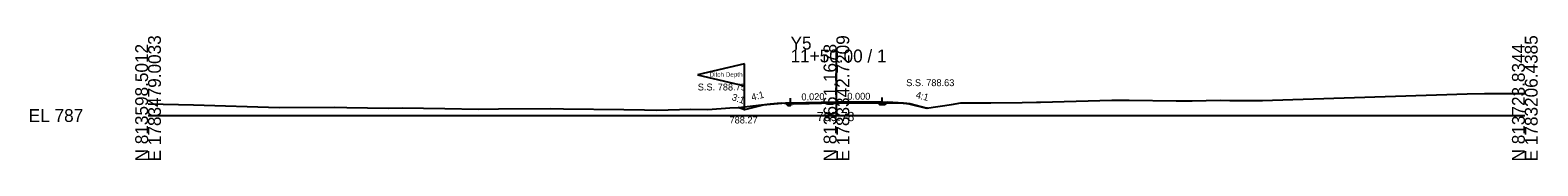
# Model space of a CAD drawing. Extents: x -26 to 1603, y -10 to 6526.
# Drawn here: x -25.7 to 302.8, y 1990.3 to 2017.3 of the extents above; entities that cross this region are included whole.
import ezdxf

# ---------------------------------------------------------------- set-up
doc = ezdxf.new("R2010")
doc.units = 0
for name, color, linetype in [('Exist Cross Section Cell', 7, 'Continuous'), ('Exist XS Center Line Elevation Label', 7, 'Continuous'), ('Exist XS Ground Line', 7, 'Continuous'), ('Prop XS Ditch Slope Text', 7, 'Continuous'), ('Prop XS Ditch Standard Text', 7, 'Continuous'), ('Prop XS Dump Level', 7, 'Continuous'), ('Prop XS Earthwork Shape', 7, 'Continuous'), ('Prop XS EOT Tick Mark', 7, 'Continuous'), ('Prop XS Finish Grade', 7, 'Continuous'), ('Prop XS Finish Grade Earthwork', 7, 'Continuous'), ('Prop XS Finish Grade Pavement', 7, 'Continuous'), ('Prop XS Pvmt Edge Slope', 7, 'Continuous'), ('Prop XS SE Text', 7, 'Continuous'), ('Prop XS Side Slope Text', 7, 'Continuous'), ('Prop XS SS Elevation Text', 7, 'Continuous'), ('Prop XS Subgrade Earthwork', 7, 'Continuous')]:
    doc.layers.add(name, color=color, linetype=linetype)

msp = doc.modelspace()

# ---------------------------------------------------------------- linework, layer by layer
at = {"layer": 'Exist Cross Section Cell'}
for p, q in [((150, 2000), (150, 2014.38)), ((0, 2000), (150, 2000)), ((150, 2000), (300, 2000))]:
    msp.add_line(p, q, dxfattribs=at)
at = {"layer": 'Exist XS Ground Line'}
for p, q in [((245.04, 2003.32), (287.47, 2004.72)), ((287.47, 2004.72), (291.25, 2004.78)), ((291.25, 2004.78), (300, 2004.79)), ((0, 2002.55), (9.93, 2002.34)), ((9.93, 2002.34), (28.54, 2001.74)), ((28.54, 2001.74), (40.53, 2001.79)), ((40.53, 2001.79), (43.29, 2001.78)), ((43.29, 2001.78), (52.34, 2001.6)), ((52.34, 2001.6), (55.39, 2001.7)), ((55.39, 2001.7), (64.65, 2001.51)), ((64.65, 2001.51), (72.02, 2001.42)), ((72.02, 2001.42), (76.39, 2001.47)), ((76.39, 2001.47), (87.61, 2001.52)), ((87.61, 2001.52), (90.51, 2001.47)), ((90.51, 2001.47), (103.64, 2001.29)), ((103.64, 2001.29), (108.15, 2001.23)), ((108.15, 2001.23), (110.85, 2001.18)), ((110.85, 2001.18), (118.3, 2001.42)), ((118.3, 2001.42), (121.96, 2001.31)), ((121.96, 2001.31), (126.77, 2001.69)), ((126.77, 2001.69), (128.69, 2001.75)), ((128.69, 2001.75), (135.59, 2002.58)), ((135.59, 2002.58), (137.08, 2002.68)), ((137.08, 2002.68), (138.08, 2002.75)), ((138.08, 2002.75), (139.86, 2002.56)), ((139.86, 2002.56), (144.06, 2002.65)), ((144.06, 2002.65), (149.46, 2002.78)), ((149.46, 2002.78), (150, 2002.78)), ((150, 2002.78), (157.1, 2002.78)), ((157.1, 2002.78), (159.36, 2002.78)), ((159.36, 2002.78), (164.53, 2002.67)), ((164.53, 2002.67), (165.17, 2002.66)), ((165.17, 2002.66), (166.06, 2002.46)), ((166.06, 2002.46), (169.65, 2001.6)), ((169.65, 2001.6), (175.04, 2002.43)), ((175.04, 2002.43), (177.1, 2002.74)), ((177.1, 2002.74), (181.03, 2002.76)), ((181.03, 2002.76), (183.63, 2002.75)), ((183.63, 2002.75), (190.47, 2002.86)), ((190.47, 2002.86), (193.6, 2002.91)), ((193.6, 2002.91), (194.44, 2002.93)), ((194.44, 2002.93), (209.99, 2003.36)), ((209.99, 2003.36), (213.76, 2003.31)), ((213.76, 2003.31), (224.01, 2003.23)), ((224.01, 2003.23), (226.75, 2003.18)), ((226.75, 2003.18), (227.52, 2003.21)), ((227.52, 2003.21), (233.65, 2003.38)), ((233.65, 2003.38), (235.73, 2003.27)), ((235.73, 2003.27), (236.35, 2003.26)), ((236.35, 2003.26), (237.09, 2003.25)), ((237.09, 2003.25), (237.57, 2003.25)), ((237.57, 2003.25), (238.46, 2003.25)), ((238.46, 2003.25), (242.81, 2003.25)), ((242.81, 2003.25), (245.04, 2003.32))]:
    msp.add_line(p, q, dxfattribs=at)
at = {"layer": 'Prop XS Dump Level'}
for p, q in [((130, 2011.27), (119.7, 2008.87)), ((130, 2006.47), (130, 2011.27)), ((119.7, 2008.87), (130, 2006.47)), ((130, 2001.27), (130, 2006.47)), ((140, 2002.75), (150, 2002.95)), ((150, 2002.95), (160, 2002.95))]:
    msp.add_line(p, q, dxfattribs=at)
at = {"layer": 'Prop XS Earthwork Shape'}
for points in [[(128.56, 2001.75), (128.69, 2001.75), (135.59, 2002.58), (137.08, 2002.68), (138.08, 2002.75), (138.9, 2002.66), (134, 2002.27), (130, 2001.27)], [(138.9, 2002.66), (139.86, 2002.56), (140, 2002.56), (140, 2002.17), (139.4, 2002.16)], [(159.39, 2002.78), (160.96, 2002.74), (160.58, 2002.37), (159.39, 2002.37)], [(160.96, 2002.74), (164.53, 2002.67), (164.64, 2002.67), (161.1, 2002.88)], [(164.64, 2002.67), (165.17, 2002.66), (165.31, 2002.63)], [(165.31, 2002.63), (166, 2002.59), (169.84, 2001.63), (169.65, 2001.6), (166.06, 2002.46)]]:
    msp.add_lwpolyline(points, close=True, dxfattribs=at)
at = {"layer": 'Prop XS EOT Tick Mark'}
for p, q in [((140, 2002.75), (140, 2003.75)), ((160, 2002.95), (160, 2003.95))]:
    msp.add_line(p, q, dxfattribs=at)
at = {"layer": 'Prop XS Finish Grade'}
for p, q in [((140, 2002.75), (138.9, 2002.66)), ((160, 2002.95), (161.1, 2002.88))]:
    msp.add_line(p, q, dxfattribs=at)
at = {"layer": 'Prop XS Finish Grade Earthwork'}
for p, q in [((130, 2001.27), (128.56, 2001.75)), ((134, 2002.27), (130, 2001.27)), ((138.9, 2002.66), (134, 2002.27)), ((161.1, 2002.88), (166, 2002.59)), ((166, 2002.59), (169.84, 2001.63))]:
    msp.add_line(p, q, dxfattribs=at)
at = {"layer": 'Prop XS Finish Grade Pavement'}
for p, q in [((140, 2002.75), (150, 2002.95)), ((150, 2002.95), (160, 2002.95))]:
    msp.add_line(p, q, dxfattribs=at)
at = {"layer": 'Prop XS Pvmt Edge Slope'}
for p, q in [((140, 2002.75), (139.4, 2002.16)), ((160, 2002.95), (160.58, 2002.37))]:
    msp.add_line(p, q, dxfattribs=at)
at = {"layer": 'Prop XS Subgrade Earthwork'}
for p, q in [((139.4, 2002.16), (138.9, 2002.66)), ((139.4, 2002.16), (140, 2002.17)), ((140, 2002.17), (140, 2002.56)), ((159.39, 2002.37), (159.39, 2002.78)), ((159.39, 2002.37), (160.58, 2002.37)), ((160.58, 2002.37), (161.1, 2002.88))]:
    msp.add_line(p, q, dxfattribs=at)

# ---------------------------------------------------------------- texts
at = {"layer": 'Exist Cross Section Cell'}
for s, p in [('E 1783479.0033', (2.8, 1990)), ('E 1783342.7209', (152.8, 1990)), ('E 1783206.4385', (302.8, 1990)), ('N 813598.5012', (0, 1990)), ('N 813661.1678', (150, 1990)), ('N 813723.8344', (300, 1990))]:
    msp.add_text(s, height=2.8, rotation=90, dxfattribs=at).set_placement(p)
for s, p in [('Y5', (140, 2014.38)), ('11+50.00 / 1', (140, 2011.58)), ('EL 787', (-26, 1998.6))]:
    msp.add_text(s, height=2.8, dxfattribs=at).set_placement(p)
at = {"layer": 'Exist XS Center Line Elevation Label'}
msp.add_text('789.78', height=2, dxfattribs=at).set_placement((145.73, 1998.78))
at = {"layer": 'Prop XS Ditch Slope Text'}
msp.add_text('4:1', height=1.5, rotation=14.0362, dxfattribs=at).set_placement((131.64, 2003.23))
at = {"layer": 'Prop XS Ditch Standard Text'}
msp.add_text('788.27', height=1.5, dxfattribs=at).set_placement((126.7, 1998.27))
at = {"layer": 'Prop XS Dump Level'}
for s, height, p in [('Ditch Depth', 1, (122.34, 2008.44)), ('Case1', 0.04, (134, 2002.23)), ('Eop', 0.3, (139.94, 2002.26)), ('Eop', 0.3, (159.39, 2002.48)), ('Case1', 0.04, (166, 2002.55))]:
    msp.add_text(s, height=height, dxfattribs=at).set_placement(p)
at = {"layer": 'Prop XS SE Text'}
for s, rotation, p in [('0.020', 1.1446, (142.38, 2003.3)), ('0.000', 360, (152.37, 2003.45))]:
    msp.add_text(s, height=1.5, rotation=rotation, dxfattribs=at).set_placement(p)
at = {"layer": 'Prop XS Side Slope Text'}
for s, rotation, p in [('3:1', 341.5651, (127.07, 2003.4)), ('4:1', 345.9638, (167.19, 2003.84))]:
    msp.add_text(s, height=1.5, rotation=rotation, dxfattribs=at).set_placement(p)
at = {"layer": 'Prop XS SS Elevation Text'}
for s, p in [('S.S. 788.63', (165.21, 2006.4)), ('S.S. 788.75', (119.78, 2005.46))]:
    msp.add_text(s, height=1.5, dxfattribs=at).set_placement(p)

doc.saveas('drawing.dxf')
